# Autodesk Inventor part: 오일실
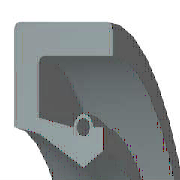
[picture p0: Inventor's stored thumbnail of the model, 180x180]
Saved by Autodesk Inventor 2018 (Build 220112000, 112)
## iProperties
IsCustomPart: 1
Created: 2015-10
Part Number: 오일실
Material: 고무
Description: 오일-실
Document SubType Name: Modeling
Standard: KS B 2804
Designer: mdu
Standards Organization: KS
Language: ko-KR
Size Designation: S - 25 38 8
Categories: <MemberInstance><Categories><Category DisplayName="샤프트 부품" InternalName="7f7aeb1f-a693-4053-b835-cee3144e0d98" Mnemonic="SHFT"><Category DisplayName="실링" Intern
Density: 0.93 g/cm^3
Appearance: 고무 - 검은색 - 버전 1.1
Author: mdu
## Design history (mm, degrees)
revolve "본체" stored, may be unused: angle "d17" = 90 deg
revolve "스프링1" stored, may be unused: angle "d18" = 90 deg
body "Solid1"
sketch "스케치1"
  geometry: L1 (0, 19)-(8, 19); L2 (8, 19)-(8, 17.75); L3 (8, 17.75)-(1.75, 17.75); L4 (0, 19)-(0, 14.6); L5 (0, 14.6)-(1.75, 14.25); L6 (1.75, 14.25)-(4.9, 12.5); L7 (4.9, 12.5)-(0, 12.5); L8 (6.3, 13.375)-(6.3, 14.6); L9 (0, 0)-(9.586, 0) reference; L10 (4.9, 12.5)-(6.3, 13.375); L11 (0, 18)-(0, -3) reference; L12 (-1.917, 0)-(11.503, 0) reference; L13 (4.2, 14.6)-(1.75, 15.09); L14 (1.75, 15.09)-(1.75, 17.75); L15 (6.3, 14.6)-(5.6, 14.6); C1 r 0.455 at (4.9, 14.6); A1 r 0.7 centre (4.9, 14.6) between (5.6, 14.6) and (4.2, 14.6)
  constraints: 26 end point, 5 horizontal alignment, 4 perpendicular, 2 centre point, 2 collinear, 2 horizontal, 2 parallel, 2 point on circle, 2 point on line, 2 vertical alignment, 1 coincident
  dimensions: "d0" = 38 diameter of L1 L9 (= SD2); "d1" = 26.75 diameter of L8.start L9 (= ABDM); "d2" = 1.25 distance of L1.end L2.end (computed from SD); "d3" = 0.91 diameter of C1 (= SPDI); "d4" = 1.4 diameter of A1 (= SPDA); "d5" = 25 diameter of L6.end L9 (= NND); "d6" = 28.5 diameter of L5.end L9 (= TKDM); "d7" = 29.2 diameter of L4.end L9 (= HLDM); "d8" = 4.9 distance from line of C1.centre L4 (= SPDST); "d9" = 6.3 distance between parallel lines of L8 L4 (= SDI); "d10" = 8 distance between parallel lines of L2 L4 (= SWDT); "d12" = 1.75 distance between parallel lines of L14 L4 (= SD)
fillet "모깎기1" dims "d11" = 0.3 (= RR)
other parameters: "SD2" = 38 [user parameter; used in 1 equation term], "SWDT" = 8 [user parameter; used in 1 equation term], "RR" = 0.3 [user parameter; used in 1 equation term], "SD" = 1.75 [user parameter; used in 2 equation terms], "NND" = 25 [user parameter; used in 1 equation term], "SPDA" = 1.4 [user parameter; used in 1 equation term], "SPDI" = 0.91 [user parameter; used in 1 equation term], "TKDM" = 28.5 [user parameter; used in 1 equation term], "HLDM" = 29.2 [user parameter; used in 1 equation term], "ABDM" = 26.75 [user parameter; used in 1 equation term], "SDI" = 6.3 [user parameter; used in 1 equation term], "SPDST" = 4.9 [user parameter; used in 1 equation term], "d13" = 0, "d14" = 0, "d15" = 0, "LAB" = 0.35 [user parameter]
